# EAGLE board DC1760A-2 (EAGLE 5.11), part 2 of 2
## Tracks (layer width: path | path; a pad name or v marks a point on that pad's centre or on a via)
+3.3V  (via drill 0.61 pad 0.61)
  Top 0.254: 21.16,60.83 C39.2 | U2.8 12.67,61.33 12.78,61.21 12.78,60.96 12.72,60.9 | U2.5 12.29,59.83 12.75,60.29 C33.2 13.16,60.33 13.04,60.33 13.04,60.58 12.72,60.9 | U2.7 12.65,60.83 12.72,60.9 | U4.7 20.53,60.83 | U4.5 19.8,59.69 19.89,59.69
  Top 0.305: 13.16,60.33 13.54,60.33
  Top 0.381: U4.8 20.52,61.33 20.53,61.21 20.53,60.83 20.53,59.94 20.28,59.69 19.89,59.69
  Top 0.406: v22.56,60.83 21.16,60.83 20.53,60.83 | L1.1 27.51,66.02 27.51,71.12 TP2.1
  Top 0.61: 13.54,60.33 v14.05,60.33
  Bottom 0.305: 21.04,60.83 20.91,60.83
  Bottom 0.61: TP2.1 27.39,64.9 23.32,60.83 v22.56,60.83 21.04,60.83 20.66,60.83 19.13,62.36 16.08,62.36 v14.05,60.33
AIN+
  Top 0.203: U9.1 29.76,27.65 29.72,27.61 27.69,27.61 27.51,27.79 R40.2 27.53,27.74
AIN-
  Top 0.203: U9.2 29.83,27.15 29.75,27.23 27.69,27.23 27.49,27.03 27.51,27 R39.2
AMP_SHDN
  Top 0.203: 9.15,28.5 9.48,28.83 12.1,28.83 12.99,27.93 U10.P3
  Top 0.254: R17.2 9.11,28.31 9.1,28.32 9.15,28.12 9.15,28.5
AMP_VOCM  (via drill 0.25, 0.3)
  Top 0.203: v9.02,25.88 8.95,26.01 9.05,25.98 11.46,25.98 11.94,26.47 11.88,26.53 C57.1 12.27,26.9 12.91,26.9 12.91,26.89 U10.P5
  Top 0.406: 17.71,35.48 R11.1 | 17.91,35.28 R9.1 | 17.71,35.48 17.91,35.28 | R10.2 17.71,35.1 17.89,35.28 17.91,35.28 | 16.67,35.48 16.68,35.47 | 16.67,35.48 17.71,35.48 | v15.86,35.41 15.92,35.47 16.66,35.47 16.67,35.48
  Route4 0.254: 9.05,25.88 v9.02,25.88 9.15,26.01 10.8,26.01 13.87,29.08 13.9,29.08 | v15.86,35.41 15.83,35.41 13.89,33.47 13.89,29.08 13.9,29.08 | 13.9,29.08 13.93,29.08
CS  (via drill 0.25)
  Top 0.127: 32.77,19.63 v32.8,19.63 32.49,19.63 32.09,20.04 32.09,21.87 31.75,22.21 U9.13
  Route4 0.203: 40.62,23.57 40.62,28.45
  Route4 0.381: 45.55,58.5 45.55,58.42 | 45.62,58.5 45.55,58.5 | J4.4 45.55,58.57 45.55,58.5
  Route4 0.406: 45.51,58.58 45.52,58.6 45.62,58.5 46.59,57.53 46.59,53.67 | 46.59,53.67 46.59,53.6 | 46.59,53.67 46.59,53.59 43.92,50.93 43.92,37.36 43.44,36.88 41.36,36.88 41.1,36.63 40.8,36.63 40.34,36.17 40.34,34.54 40.62,34.27 40.62,28.45 | v39.86,16.49 39.81,16.49 39.81,16.56 40.62,17.37 40.62,23.57 40.62,23.55
  Bottom 0.254: R1.5 43.91,16.02 43.44,16.49 v39.86,16.49 39.86,16.46 35.97,16.46 v32.8,19.63
EXTREF  (via drill 0.25)
  Top 0.127: 28.05,31.39 29.55,31.39 30.84,30.1 30.84,29.06 31.25,28.65 U9.39
  Top 0.254: 25.79,34.77 25.79,34.75 | 25.79,34.77 25.79,39.5 v25.74,39.55 | 25.79,34.77 25.79,34.06 28.17,31.67 28.28,31.78 C17.1 28.28,31.73 28.05,31.5 28.05,31.39
  Bottom 0.254: R14.1 25.34,38.7 25.23,38.61 25.81,39.19 25.81,39.55 | v25.74,39.55 25.81,39.55 | TP1.1 24.09,42.14 24.11,42.16 24.09,42.16 24.03,42.11 24.03,41.35 25.81,39.55
GND  (via drill 0.25, 0.3, 0.41, 0.51, 0.61)  (6 unrouted)
  Top 0.127: 64.34,29.17 64.34,29.08 64.29,29.13 | 63.94,6.76 63.96,6.73 | v63.51,6.76 63.94,6.76 | 63.64,6.77 63.92,6.77 63.94,6.76 | 31.83,25.02 31.83,24.26 31.63,24.05
  Top 0.203: v63.73,45.95 63.71,45.97 J1.6 | 64.32,43.56 64.31,43.57 | 64.32,43.56 63.63,43.56 v63.61,43.59 | J1.12 64.32,43.56 | 65.64,38.74 65.74,38.74 | 65.64,38.74 J1.24 | v63.76,38.76 63.79,38.74 65.64,38.74 | J1.18 65.61,41.15 64.6,41.15 | 64.14,41.15 64.6,41.15 | v63.73,41.17 64.57,41.17 64.6,41.15 | 65.61,31.62 | 65.61,31.62 J1.42 | 64.42,31.55 65.54,31.55 65.61,31.62
  Top 0.254: 63.85,33.95 64.23,33.95 | 64.42,31.55 | v63.76,31.55 | v63.66,13.97 v63.65,13.97 | 63.74,29.17 63.79,29.21 v63.81,29.21 | 63.74,29.17 J1.48 | 63.74,29.17 63.73,29.16 | U9.3 28.61,26.65 v28.4,26.44 | v41.36,35.08 41.36,35.05 42.16,35.05 C35.2 | 8.03,58.62 7.7,58.62 7.7,57.91
  Top 0.305: 65.61,33.91 | 65.61,33.91 J1.36 63.89,33.97 63.84,33.91 v63.81,33.93 | 63.85,33.95 65.57,33.95 65.61,33.91 | 63.88,36.37 64.65,36.37 J1.30 | 63.68,26.7 63.68,26.72 65.57,26.72 J1.54 | C47.1 17.89,25.61 17.81,25.55 17.81,25.96 17.63,26.14 | 17.94,29.24 17.9,29.2 C45.1 17.79,28.88 17.61,28.7 v17.68,28.7 | 17.63,26.14 17.61,26.16 | 17.63,26.14 v17.66,26.14 | v18.32,26.44 18.35,26.44 18.74,26.05 C48.1 | v18.32,28.37 18.32,28.4 18.8,28.88 C46.1
  Top 0.356: 64.65,36.37 64.65,36.35 64.62,36.37 v63.94,36.37
  Top 0.406: 64.31,43.57 63.95,43.57 | 64.14,41.15 63.81,41.15 | 64.23,33.95 64.17,33.88 | v63.76,31.55 64.42,31.55 | 63.79,29.17 64.34,29.17 J1.48 | 64.98,11.56 v63.66,11.56 | 65.49,11.56 64.98,11.56 | 65.61,11.56 65.49,11.56 | 65.49,11.56 65.5,11.57 64.99,11.57 64.98,11.56 | J1.90 65.61,9.15 65.61,9.14 65.59,9.12 v63.66,9.12 | 65.61,11.56 J1.84 | 65.61,11.56 64.98,11.56 | v63.66,13.97 63.71,13.97 J1.78 | 65.61,6.73 | 65.61,6.73 J1.96 | 63.64,6.77 65.57,6.77 65.61,6.73 | R47.2 10.44,18.74 v10.78,19.08 | v7.65,58.09 7.96,58.04 7.96,58.62 8.03,58.62 8.08,58.67 8.03,58.73 R31.2
  Top 0.508: J1.60 65.53,21.17 65.49,21.21 65.46,21.18 v63.71,21.18 | 65.61,18.79 65.61,18.8 | J1.66 65.61,18.79 | v63.81,18.77 65.59,18.77 65.61,18.79 | J1.72 65.51,16.37 65.49,16.38 65.46,16.36 v63.71,16.36
  L2-GND 1.016: 23.32,-0.51 23.32,1.27
  Route3 1.016: 23.32,1.14 23.32,-0.51
  Route4 1.016: 23.32,1.02 23.32,-0.51
  L15-GND 1.016: 23.32,1.27 23.32,-0.51
  Bottom 0.127: 65.61,36.35 65.67,36.3 | 65.61,36.35 J1.30 | v63.94,36.37 65.59,36.37 65.61,36.35 | U1.3 59.9,13.85 59.57,14.17 v59.57,14.73 | C41.2 50.35,10.59
  Bottom 0.203: 63.35,28.98 v63.81,29.21 | 65.55,29.16 J1.48 | 65.64,29.97 J1.45 | 65.49,31.37 J1.42 | 65.49,31.37 63.46,31.37 | J1.37 65.49,32.97 63.79,32.97 | 63.35,33.78 v63.81,33.93 | 65.53,33.96 J1.36 | v63.76,31.55 arc90 63.58,31.37 v63.76,31.55 | J1.39 63.54,32.17 63.53,32.18 | 63.58,32.97 | 63.63,34.57 | 63.53,35.36 63.55,35.37 | 63.42,36.97 63.4,36.98 | 63.51,37.77 | 63.37,38.57 v63.76,38.76 | 63.38,39.37 | 63.43,40.18 63.44,40.17 | 63.46,40.97 v63.73,41.17 | 63.75,41.97 63.73,41.73 | 63.74,42.57 63.71,42.55 63.58,42.55 | 63.54,43.37 v63.61,43.59 | 63.51,44.35 63.51,44.17 | 63.49,44.97 63.48,44.96 63.46,44.98 | 65.49,31.37 63.58,31.37 v63.76,31.55 | 63.46,30.61 63.49,30.57 | v63.58,22.61 63.57,22.75 | 63.33,21.84 63.49,21.95 63.53,21.97 | 63.46,20.07 63.59,20.35 | 63.54,19.57 63.46,19.43 | 63.46,17.78 63.41,17.92 | 63.4,17.17 63.33,17.02 | 63.41,16.35 v63.71,16.36 | 63.46,15.37 63.46,15.57 | 63.59,14.77 63.58,14.61 | 63.4,14 v63.66,13.97 | 63.46,12.95 63.5,13.17 | 63.5,12.37 63.46,12.19 | v63.66,9.12 63.71,9.17 65.58,9.17 65.61,9.15 | v63.51,6.76 63.46,6.77 65.57,6.77 65.61,6.73 | 65.61,9.15 65.61,9.14 | 65.61,9.15 J1.90 | 65.61,6.73 | 65.61,6.73 J1.96 | 64.73,11.56 | 64.73,11.56 64.73,11.57 | 64.62,11.56 64.73,11.56 | 59.42,13.84 59.39,13.85 U1.2 59.31,13.85 U1.1 | 59.9,13.84 59.9,13.85 | 59.9,13.85 59.9,13.84 | U1.4 60.66,13.85 60.66,13.84 | 59.97,13.86 59.98,13.87 | U1.3 59.97,13.86 | 59.9,13.84 59.92,13.84 59.95,13.84 59.97,13.86
  Bottom 0.254: 63.83,47.57 63.58,47.32 63.58,46.61 | 63.58,46.61 63.58,46.08 63.71,45.95 | 63.58,46.61 63.61,46.61 63.76,46.77
  Bottom 0.305: 65.61,36.32 J1.30 | U1.7 59.32,8.96 59.14,9.14 57.61,9.14 57.49,9.02 57.36,9.02 57.4,8.98 C27.2 | 63.66,26.7 65.54,26.7 J1.54 | J1.54 65.61,26.75 | J1.54 J1.51 65.59,27.54 65.59,26.92 65.64,26.98 65.64,28.35 65.63,28.35 J1.49 | U7.7 48.62,9.53 | 47.99,8.26 U7.9 49.26,8.13 | U7.6 48.75,10.16 49.03,9.88 49.69,9.88 | U7.15 42.37,10.16 42.75,10.54 42.75,12.07 42.7,12.12 v42.68,12.09
  Bottom 0.406: 63.75,41.97 63.75,41.21 63.73,41.2 v63.73,41.17 | U1.2 59.42,13.84 59.92,13.84 59.9,13.85 | J1.85 62.27,10.77 60.48,12.55 60.48,13.79 60.54,13.85 U1.4 60.46,13.85 60.46,13.84 60.45,13.85 U1.3
  Bottom 0.508: 63.71,29.16 65.55,29.16 | 63.48,29.97 65.64,29.97 | 63.78,33.17 J1.37 | 63.79,33.96 65.53,33.96 | 63.68,34.77 J1.33 | 63.69,35.57 J1.31 | 63.56,37.17 J1.27 | 63.43,37.97 J1.25 | 63.66,38.77 J1.24 | 63.61,39.55 J1.21 | 63.61,40.37 J1.19 | 63.55,41.17 J1.18 | 63.75,41.97 65.47,41.97 | 63.81,42.77 J1.13 | 63.63,43.56 J1.12 | 63.51,44.35 J1.9 | 63.63,45.16 J1.7 | 63.68,31.57 J1.42 | 63.61,30.76 J1.43 | 63.57,22.75 J1.55 | 63.53,21.97 J1.57 | 63.57,21.17 J1.60 | 63.59,20.35 J1.61 | 63.54,19.57 J1.63 | J1.66 64.47,18.75 v63.81,18.77 | 63.41,17.92 J1.67 | 63.4,17.17 J1.69 | 63.41,16.35 J1.72 | 63.46,15.57 J1.73 | J1.75 63.59,14.77 | 63.4,14 J1.78 | 63.5,13.17 64.67,13.17 | 64.67,13.18 J1.79 | 64.63,11.57 64.73,11.57 J1.84 | v63.66,11.56 64.62,11.56 | 63.83,47.57 J1.1 | 63.76,46.77 J1.3 | J1.6 63.73,45.97 | 63.55,32.37 J1.39 | 63.5,12.37 63.58,12.37 63.59,12.37 J1.81 | R20.2 32.34,9.65 32.34,10.16 v32.57,10.39
  Bottom 0.61: v63.81,29.21 63.71,29.16 | 63.48,29.97 63.38,29.77 | 63.58,32.97 63.78,33.17 | v63.81,33.93 63.79,33.96 | 63.63,34.57 63.51,34.6 63.68,34.77 | 63.55,35.37 63.56,35.43 63.69,35.57 | 63.42,36.97 63.56,37.16 63.56,37.17 | 63.51,37.77 63.51,37.9 63.43,37.97 | 63.37,38.57 63.63,38.74 63.66,38.77 | 63.38,39.37 63.43,39.37 63.61,39.55 | 63.44,40.17 63.53,40.28 63.61,40.37 | 63.46,40.97 63.46,41.07 63.55,41.17 | 65.47,41.97 65.49,41.96 J1.15 | 63.74,42.57 63.74,42.7 63.81,42.77 | 63.54,43.37 63.54,43.47 63.63,43.56 | 63.49,44.97 63.49,45.02 63.63,45.16 | 63.58,31.37 63.58,31.47 63.68,31.57 | 63.49,30.57 63.49,30.64 63.61,30.76 | 63.57,21.17 v63.71,21.18 | 64.67,13.17 64.67,13.18 | 63.73,45.97 63.71,45.95 | 63.71,42.55 63.71,42.01 63.75,41.97 | 63.58,32.97 63.58,32.94 63.56,32.92 63.55,32.37 | 63.49,21.95 63.49,21.96 63.48,21.97 63.58,22.07 v63.58,22.61 | 63.46,15.37 63.46,15.29 63.43,15.27 63.59,15.1 63.59,14.77
  other vias: 28.23,34.72 29.17,37.59 28.71,38.74 34.93,37.82 29.24,44.3 32.42,36.86 46.69,34.95 42.91,42.24 43.01,41.4 42.55,37.87 50.35,11.43 49.05,19.13 15.17,17.12 14.13,51.82 9.23,11.79 15.5,7.26 28.23,8 15.5,9.3 15.5,10.19 15.63,11.07 13.98,16.41 3.05,28.73 48.47,17.17 48.7,14.88 54.64,10.08 54.97,7.52 59.29,12.22 35.59,35.2 32.57,41.02 32.21,35.2 20.99,38.35 20.22,69.06 17.76,39.14 17.91,54.28 22.23,50.44 17.86,45.97 19.01,39.17 36.25,40.06 38.08,38.2 37.78,39.67 37.8,40.64 40.42,43.26 37.04,39.17 41.51,39.09 26.75,36.25 24.95,35.15 21.85,34.9 24.57,35.66 20.43,43 21.8,47.35 19.16,69.93 19.16,71.32 19.16,72.72 19.16,73.99 8.52,74.07 7.22,73.99 11.41,73.99 9.76,73.99 8.11,72.72 2.5,9.04 1.99,8.1 3.38,8.51 1.1,7.37 4.96,8.59 0.97,8.76 8.21,5.94 7.07,1.02 8.59,4.06 9.61,4.45 10.88,3.81 12.15,1.91 13.42,1.91 14.69,1.91 15.96,1.91 19.97,15.88 17.51,38.07 30.36,69.32 29.04,73.86 27.72,73.89 32.65,50.14 31.38,53.42 27.64,50.57 28.33,52.86 27.26,62.71 31.07,42.44 35.29,69.67 36.05,70.18 36.81,70.94 37.57,71.7 38.46,72.59 46.41,38.38 42.27,42.49 45.83,35.69 46.62,35.66 41.28,35.81 41.99,35.81 44.91,42.24 44.91,43.66 59.8,67.61 48.24,73.1 46.97,73.1 45.7,73.1 44.43,73.1 43.16,73.1 41.89,73.1 40.62,73.1 39.48,73.1 40.72,42.19 42.83,39.98 44.91,41.43 37.55,35.18 41.61,38.18 41.64,1.02 43.26,0.97 50.65,6.58 42.5,2.67 50.65,2.08 45.02,8.41 50.76,0.89 52.03,0.89 53.3,0.89 54.69,0.89 55.84,0.89 57.23,0.89 58.5,0.89 59.65,1.65 60.28,2.41 58.48,2.62 53.4,2.59 54.95,3.81 52.15,7.52 49.13,8.1 50.3,7.7 46.92,8.71 53.8,17.25 59.65,11.68 46.39,39.34 41.87,40.59 41.94,41.3 60.31,10.16 59.11,17.91 54.44,16.84 54.9,16.18 48.42,44.27 39.15,36.63 40.57,38.56 39.73,37.47 55.84,3.02 46.49,14.76 42.7,12.88 43.01,14.73 30.08,46.38 25.79,47.75 29.45,47.85 28.23,45.34 27.77,48.54 27.26,46.33 30.31,43.31 30.87,36.86 26.9,38.81 34.75,35.76 0.84,67.01 30.36,72.36 33.74,43.64 32.72,40.13 35.21,45.09 35.64,37.87 35.85,41.78 36.4,43.28 31.55,50.06 26.32,40.82 30.38,38.74 19.72,45.95 30.44,37.52 32.87,38.96 33.76,42.6 32.39,44.04 33.28,45.31 30.38,70.97 16.36,16.74 14.94,15.34 0.87,31.14 16.31,12.12 24.52,36.4 24.49,37.19 21.72,37.67 23.88,45.47 20.28,39.24 25.81,50.47 18.78,37.97 15.27,51.79 15.02,45.67 27.87,37.31 18.4,43.31 12.78,53.19 11.46,54.38 24.82,44.4 24.49,48.08 21.88,35.74 13.09,16.28 9.25,44.65 9.73,45.49 42.55,19.56 33.79,44.65 32.59,46.08 32.59,47.45 32.62,48.9 32.65,51.36 32.65,52.68 32.65,54.03 32.65,55.17 32.65,56.34 32.14,57.3 31.35,58.06 30.46,58.93 30.41,60.02 30.49,61.19 28.28,63.63 30.44,62.23 30.49,63.27 30.46,64.39 30.36,67.34 28.89,64.41 26.27,58.67 24.64,58.7 25.36,60.78 24.77,60.05 26.8,54.28 26.35,61.8 22.87,59.23 20.68,62.87 25.13,64.57 25.84,65.28 25.08,67.44 25.94,67.44 24.95,73.89 26.35,73.91 22.31,67.54 20.96,67.54 18.19,63.75 21.95,62.15 19.49,67.56 22.74,62.2 23.45,57.53 23.5,56.31 17.3,58.95 22.54,45.95 23.63,54.74 23.6,53.64 23.63,48.84 35.36,40.92 35.21,46.43 35.24,47.5 35.21,48.67 35.26,49.94 35.29,51.23 35.34,52.68 35.29,54 35.26,55.45 35.26,56.79 35.26,58.17 35.21,59.39 35.21,62.33 35.26,63.3 35.24,64.24 35.24,65.23 35.19,66.27 35.26,68.78 58.32,66.73 56.57,66.55 55,67.01 53.7,67.92 52.97,69.09 14.46,14.76 59.8,65.46 59.8,64.14 59.8,62.46 59.8,60.96 59.75,59.64 59.8,58.32 59.92,56.67 59.92,54.99 59.95,53.67 59.9,52.32 60.08,50.93 59.95,49.48 59.98,47.88 59.98,46.61 59.32,46.13 17.79,73.99 16.21,74.04 14.64,74.09 13.14,74.04 18.24,67.49 18.22,66.22 18.24,64.87 21.22,58.93 18.12,58.12 23.48,58.72 21.65,55.91 21.88,54.48 17.86,55.58 22.79,53.54 11.77,8.79 16.59,48.62 21.77,48.31 1.07,46.99 1.12,48.31 1.15,51.05 1.12,53.82 1.12,55.17 1.17,56.79 1.12,58.37 1.17,59.97 2.09,59.97 0.92,66.04 0.9,68.05 5.77,66.88 8.01,69.01 39.05,41.5 38.31,41.48 39.6,49.12 50.45,49.3 38.74,61.98 39.22,67.08 42.7,43.74 41.36,45.14 42.83,49.23 44.91,47.55 50.5,46.63 50.48,47.55 52.05,46.99 55.78,48.49 55.71,46.89 57.54,46.91 42.68,51.92 49.59,61.54 42.73,64.49 42.65,70.05 46.31,67.21 55,62.18 48.6,56.82 44.81,49.89 54.84,62.97 41.74,62.18 49.77,64.14 49.31,70.21 52.23,67.18 46.62,62.46 52.99,62.74 51.52,54.05 57.33,58.29 48.55,58.39 56.88,63.78 42.98,43.13 42.68,44.58 58.12,46.02 58.12,46.99 56.57,55.55 56.57,53.98 57.61,55.63 55.94,47.78 52.81,16 15.78,57.79 14.15,54.28 15.27,53.24 14.08,53.21 16.06,39.45 12.17,43.15 9.86,47.73 12.81,54.31 12.86,55.42 12.58,62.51 9.38,49.1 10.12,50.47 7.98,48.29 7.32,54.86 6.08,53.44 3,57.58 4.17,54.81 8.08,46.33 5.72,46.18 11.46,55.52 43.69,7.59 42.78,6.17 41.61,3.23 21.8,36.78 19.64,36.68 19.87,38.07 19.16,41.94 37.8,36.63 40.65,37.59 35.62,35.94 35.26,36.63 44.89,43 29.8,36.09 11.28,49.28 20.91,44.93 29.78,39.62 26.65,37.54 31.6,46.46 31.38,55.09 29.67,51.64 26.65,49.63 30.31,50.62 11.74,36.88 10.29,55.47 9.07,51.54 11.28,37.67 15.07,38.18 15.09,36.75 17.74,32.54 2.88,45.85 7.3,53.87 16.26,38.46 16.62,50.19 1.07,15.16 6.38,12.47 2.5,10.85 1.12,10.74 7.37,7.19 6.33,8.1 8.01,9.7 4.32,10.64 6.18,10.9 6.33,13.79 4.27,15.16 1.91,19.3 9.58,16.1 62.9,6.96 61.37,15.29 62.92,11.99 62.9,14.33 63.05,16.03 62.8,17.07 63.05,20.09 62.87,20.9 61.07,6.3 62.87,4.95 61.47,10.06 62.19,12.65 62.16,14.94 62.21,17.65 44.91,46.79 63.23,33.68 44.91,45.16 45.6,45.09 46.11,46.18 62.87,41.17 46.01,46.86 62.59,47.27 61.86,46.56 63.33,47.65 61.93,47.68 61.17,47.68 45.17,46.05 60.53,21.77 62.41,20.35 62.49,16.46 9.63,10.74 24.44,1.02 12.45,40.21 19.56,51.26 11.44,56.62 8.06,52.5 12.78,56.64 15.22,50.22 24.54,51.77 20.61,37.24 41.64,19.53 63.53,17.2 50.7,17.6 47.58,17.09 28.96,34.72 31.78,41.76 27.21,41.53 28.35,40.26 26.96,40.01 50.6,40.39 50.58,42.21 50.48,45.09 50.55,43.71 51.11,44.32 51.24,41.12 50.6,39.22 42.5,45.36 46.49,45.19 48.42,46.38 51.75,45.36 51.64,42.7 55.68,45.21 56.8,45.36 44.86,48.64 42.68,46.38 46.36,44.02 37.88,47.47 41.56,48.18 39.45,46.15 38.69,51.49 41.1,50.72 37.9,53.04 11.59,62.46 10.67,62.43 11.59,63.3 10.65,63.32 11.11,58.7 10.19,57.71 10.19,58.72 11.33,57.71 10.19,56.57 4.68,55.52 5.57,55.52 6.46,55.52 21.95,66.07 21.95,65.05 21.95,64.16 21.95,63.27 3.79,55.52 18.9,58.93 18.14,58.93 18.88,58.12 12.5,63.37 7.09,67.77 11.16,46.13 5.11,54.81 5.98,54.79 6.28,56.39 3.05,56.41 12.66,48.01 1.07,49.71 15.02,42.57 8.97,8.56 10.5,7.04 9.23,6.65 8.69,16.1 52.89,12.85 55.71,12.95 52.79,10.54 54.95,14.22 45.7,41.99 46.39,42.77 61.02,46.13 58.25,24.13 28.86,67.36 25.15,66.27 29.65,67.31 25.89,66.27 21.09,62.23 24.01,59.44 13.11,58.72 12.35,58.72 13.87,58.72 21.88,58.93 20.61,58.95 13.49,61.82 18.62,44.5 37.42,24.94 31.4,31.19 28.51,29.77 25.53,24.13 25.53,23.29 48.01,27.08 29.09,28.35 28.4,28.35 26.37,28.78 25.53,24.87 22.31,24.66 22.46,30.07 36.07,22.15 38.11,30.12 30.03,21.67 26.63,24.16 28.89,19.84 28.2,19.84 27.69,20.19 38.18,24.92 38.89,24.92 39,25.78 39.2,30.4 41.74,27.38 36.68,25.12 32.59,31.24 33.15,30.48 30.71,31.09 28.38,29.13 27.57,34.72 42.55,28.93 41.79,28.93 43.26,32.31 44.48,32.28 43.82,31.62 43.21,30.91 44.46,30.86 43.87,30.25 43.26,24.18 44.46,24.16 43.85,23.44 43.24,22.81 44.46,22.83 43.87,22.15 42.5,27.38 41.71,26.7 45.65,27.33 46.39,26.54 46.39,27.28 52.71,1.78 53.37,1.93 31.78,19.56 29.67,21.18 26.12,26.01 25.53,26.04 24.85,26.01 29.09,26.44 25.69,28.78 25,28.78 24.34,29.08 23.78,29.64 23.15,30 24.21,25.6 23.7,25.04 23.04,24.69 21.11,24.71 20.94,23.95 20.3,23.44 20.28,20.5 18.5,17.88 16.11,18.06 15.22,18.67 14.41,20.24 11.21,17.55 11.84,18.24 13.8,20.47 11.79,20.37 11.74,21.18 11.82,19.69 11.79,19 10.39,16.46 7.98,16.08 6.13,15.19 5.32,15.19 2.98,15.16 0.97,19.33 3.03,19.3 4.3,19.3 5.49,19.3 6.33,19.89 6.31,20.88 6.33,22.07 6.33,23.34 6.33,24.87 6.33,26.42 6.71,28.17 6.71,29.85 6.71,31.32 6.71,32.89 6.71,34.29 5.75,35.59 4.5,35.61 3.18,35.59 1.4,35.61 1.15,39.55 3.08,39.55 4.5,39.52 5.9,39.52 9.81,41.96 9.84,39.65 11.54,39.5 11.97,37.57 15.07,39.27 11.77,36.07 11.77,35.41 9.33,40.84 11.79,34.75 15.98,36.68 15.78,32.46 18.22,33.1 18.95,32.89 18.62,33.73 19.95,32.84 20.53,33.48 21.19,33.05 19.56,49.3 25.08,30.56 24.44,2.29 24.44,3.56 24.44,4.83 24.44,6.1 28.51,6.15 28.51,4.88 28.51,3.61 28.51,2.34 28.51,1.07 25.33,6.55 26.6,6.55 27.87,6.55 33.03,2.51 33.03,3.78 33.03,5.05 33.03,6.32 34.3,6.45 35.59,6.43 36.84,6.32 36.96,5.05 36.96,3.78 36.96,2.51 36.96,1.24 33.03,1.24 28.73,8.51 28.99,10.29 28.96,11.33 28.96,12.34 28.96,13.61 28.96,14.88 28.96,16.15 28.96,17.42 28.96,18.44 29.55,19.23 32.82,8.03 32.95,9.42 32.54,11.33 35.06,11.35 32.54,12.34 32.54,13.61 32.54,14.88 32.54,16.15 32.54,17.17 32.42,18.57 31.93,18.97 50.65,37.82 52.05,39.24 53.83,41.05 56.09,43.31 57.72,44.93 50.88,21.89 52.79,23.83 53.7,24.74 55.68,26.75 56.88,27.69 58.93,27.71 59.87,27.58 51.37,30.84 55.84,19.84 54.36,21.54 57.54,21.13 56.95,16.61 40.16,1.65 40.16,3.48 40.24,5.99 40.21,8.18 40.27,10.08 40.16,12.07 38.69,13.61 37.55,14.91 40.6,14.73 39.99,13.69 25.03,15.24 22.21,11.3 20.96,11.73 18.62,10.19 19.72,14.25 22.03,19.28 22.84,15.52 19.46,18.9 24.09,19.94 25.41,19.05 24.11,17.5 24.95,20.96 22.89,20.47 20.28,18.01 17.25,18.08 14.59,18.75 10.73,17.09 17.81,12.12 24.8,9.65 24.26,13.18 27.67,12.4 21.6,8.71 21.16,6.02 17.23,1.91 18.5,1.91 19.77,1.91 21.04,1.91 22.31,1.91 22.82,2.51 22.84,5.03 22.84,6.3 22.84,7.57 24.06,7.98 25.2,7.98 26.35,7.98 27.36,7.98 17.74,14.48 2.5,26.49 4.07,24.89 4.96,28.47 1.66,28.24 1.68,24.82 4.2,26.67 1.17,43.94 1.07,45.62 2.44,43.94 3.71,43.94 4.98,43.94 6.25,43.94 6.25,40.13 6.51,41.4 8.26,44.91 8.26,43.64 8.24,41.83 8.44,39.95 10.9,40.84 20.76,50.8 27.74,55.17 33.84,8.03 35.11,8.03 36.38,8.03 33.53,13.87 34.73,12.67 35.95,11.46 36.58,10.06 52.71,31.62 53.83,32.66 55.78,34.37 56.95,35.84 58.3,37.24 59.42,38.51 58.1,38.58 61.91,38.76 60.97,38.76 56.67,38.61 55.71,37.47 53.63,35.64 53.17,34.98 52.33,34.26 51.57,33.45 50.73,32.64 50.65,31.67 59.19,31.6 61.42,31.55 59.57,34.01 61.88,33.93 60.59,36.5 62.54,36.47 59.67,43.64 61.93,43.61 58.66,41.15 61.3,41.17 6.51,42.67 31.35,27.03 32.37,27.03 33.38,27.03 34.4,27.03 34.4,26.01 34.4,24.99 34.4,23.98 31.35,26.01 31.35,24.99 31.35,23.98 32.37,23.98 32.37,24.99 32.37,26.01 33.38,26.01 33.38,24.99 33.38,23.98 39.91,24.92 39.91,25.76 39.91,27.13 42.04,25.68 41.36,25.68 10.24,26.59 17.41,27.48 37.19,30.73 36.89,29.21 36.4,28.7 39.78,30.86 38.49,30.81 37.47,29.72 37.09,21.44 36.63,20.96 37.88,21.54 37.45,20.9 36.58,20.17 27.03,28.78 27.72,28.78 27.49,26.01 26.83,26.04 10.8,35.74 10.73,34.32 10.75,19.89 12.81,26.29 12.76,29.24 18.19,27.41 18.88,27.41 19.59,27.43 20.25,27.46 20.96,27.28 17.02,28.22 16.67,25.96 16.97,26.7 16.62,28.91 12.15,25.73 15.3,26.16 15.12,28.55 19.62,23.44 18.9,23.44 18.19,23.44 17.51,23.47 16.82,23.47 16.14,23.47 15.45,23.44 14.61,22.45 15.45,22.63 13.8,22.2 12.81,22.17 12.07,22.2 10.39,22.81 12.71,21.46 10.8,22.38 11.44,22.25 20.81,31.32 23.07,30.96 20.07,31.37 19.36,31.34 18.62,31.34 17.94,31.34 17.2,31.34 16.49,31.37 15.81,31.34 15.2,31.57 15.12,32.26 10.78,39.01 12.76,32.99 11.79,41.73 11.82,33.93 11.54,32.28 10.55,31.95 11.03,32.82 11.82,33.2 10.62,37.74 10.01,38.02 9.53,38.56 8.85,38.66 8.19,38.66 6.74,38.71 7.88,36.45 8.36,35.89 8.36,35.13 8.36,34.29 8.36,33.43 8.36,32.72 8.36,31.93 8.36,31.24 8.39,30.53 8.72,29.79 7.98,18.44 8.36,18.95 8.34,19.66 8.34,20.37 8.36,21.13 8.36,21.87 8.36,22.61 8.34,23.39 8.31,24.08 8.31,24.77 8.24,25.35 17.05,21.26 21.44,21.97 23.32,22.58 17.1,20.22 18.35,16.31 9.89,13.77 22.41,13.54 27.79,16.03 12.71,35.28 12.71,37.47 12.73,38.25 16.77,32.39 21.22,31.83 21.62,32.41 24.26,31.04 24.87,29.67 26.02,29.57 12.71,44.32 48.37,52.22 51.87,51.38 53.75,51.41 44.38,53.47 39.2,54.71 39.22,64.85 46.92,65.51 53.37,66.04 45.42,71.25 10.75,28.27 10.04,28.27 9.96,27.53 9.53,26.62 10.85,35 10.73,20.6 13.93,27.76 13.93,27.03 12.71,32.26 9.81,25.3 11.36,25.43 10.62,25.3 9.86,29.39 10.75,29.39 11.69,29.39 60.03,24.89 60.03,23.88 60.53,22.86 61.55,22.61 62.57,22.61 60.03,25.91 60.53,26.67 61.55,26.67 62.57,26.67 63.58,26.67 15.07,57.79 6.51,58.85
  pour Bottom (isolate 0.254, no thermals): 0.59,74.42 0.59,0.51 37.29,0.51 37.29,11.05 33.36,14.99 33.36,38.1 34.12,38.86 34.12,45.72 33.1,46.74 33.1,57.15 30.82,59.44 30.82,72.9 29.29,74.42
  pour Bottom (isolate 0.254, no thermals): 34.88,38.35 34.37,37.85 34.37,29.46 33.36,28.45 33.36,21.84 34.37,20.83 34.37,16.76 39.71,11.43 39.71,0.51 60.53,0.51 60.53,4.57 64.09,4.57 64.09,23.11 61.3,23.11 arc-90 60.53,23.88 60.53,25.65 arc-90 61.3,26.42 64.09,26.42 64.09,48.01 60.53,48.01 60.53,74.42 39.2,74.42 34.88,70.1
  pour Top (rank 2, no thermals): 33.38,14.81 33.36,20.78 33.41,21.54 33.48,28.63 33.46,32.05 33.46,38.2 34.14,38.89 34.14,45.11 33.15,46.08
  pour L2-GND (isolate 0.381, rank 2): 0.59,74.42 60.53,74.42 60.53,48.26 67.14,48.26 67.14,26.42 61.3,26.42 arc90 60.53,25.65 60.53,23.88 arc90 61.3,23.11 67.14,23.11 67.14,4.57 60.53,4.57 60.53,0.51 0.59,0.51 0.59,15.75 6.18,15.75 6.94,16.51 9.48,16.51 9.99,17.02 9.99,23.11 10.24,23.37 13.54,23.37 13.8,23.62 13.8,24.89 13.54,25.15 9.23,25.15 8.72,24.64 8.72,18.54 8.21,18.03 6.94,18.03 6.18,18.8 0.59,18.8 0.59,36.07 5.92,36.07 6.69,36.83 8.21,36.83 8.72,36.32 8.72,30.23 9.23,29.72 13.8,29.72 13.8,31.5 10.24,31.5 9.99,31.75 9.99,37.34 8.97,38.35 6.69,38.35 5.92,39.12 0.59,39.12
  pour Route3 (isolate 0.381, rank 2): 0.59,59.06 23.2,59.06 23.2,74.42 60.53,74.42 60.53,48.26 67.14,48.26 67.14,26.42 61.3,26.42 arc90 60.53,25.65 60.53,23.88 arc90 61.3,23.11 67.14,23.11 67.14,4.57 60.53,4.57 60.53,0.51 0.59,0.51
  pour Route4 (isolate 0.381): 0.59,74.42 60.53,74.42 60.53,48.26 67.14,48.26 67.14,26.42 61.3,26.42 arc90 60.53,25.65 60.53,23.88 arc90 61.3,23.11 67.14,23.11 67.14,4.57 60.53,4.57 60.53,0.51 0.59,0.51
  pour L15-GND (isolate 0.381): 0.59,74.42 60.53,74.42 60.53,48.26 67.14,48.26 67.14,26.42 61.3,26.42 arc90 60.53,25.65 60.53,23.88 arc90 61.3,23.11 67.14,23.11 67.14,4.57 60.53,4.57 60.53,0.51 31.83,0.51 31.83,18.54 29.8,18.54 29.8,0.51 0.59,0.51
  pour Top (rank 2, no thermals): 0.59,74.42 0.59,0.51 37.29,0.51 37.29,11.05 33.36,14.99 33.36,38.1 34.12,38.86 34.12,45.72 33.1,46.74 33.1,57.15 30.82,59.44 30.82,72.9 29.29,74.42
  pour Top (no thermals): 34.88,38.35 34.37,37.85 34.37,29.46 33.36,28.45 33.36,21.84 34.37,20.83 34.37,16.76 39.71,11.43 39.71,0.51 60.53,0.51 60.53,4.57 64.09,4.57 64.09,23.11 61.3,23.11 arc-90 60.53,23.88 60.53,25.65 arc-90 61.3,26.42 64.09,26.42 64.09,48.01 60.53,48.01 60.53,74.42 39.2,74.42 34.88,70.1
N$1
  Bottom 0.254: R1.1 45.5,14.96 45.75,14.71 45.75,8.38 46.51,7.62 U7.10
N$2  (via drill 0.3 pad 0.61)
  Top 0.254: U9.11 30.75,20.57 v30.69,20.57
  Bottom 0.508: 30.69,9.4 v30.69,20.57 | 30.69,9.4 R20.1 | 30.69,9.4 R13.1 | R19.2 30.69,9.4
N$3  (via drill 0.25)
  Top 0.127: 55.96,4.83 R24.2 55.9,4.77 | 55.96,4.83 56.02,4.77 56.66,4.77 56.98,4.45 v56.98,3.81 | 55.9,4.77 55.96,4.83 | 55.9,4.77 55.84,4.7 U6.2 53.22,4.7
  Bottom 0.127: 65.36,5.08 65.49,4.95 J1.99 65.61,5.21 | 65.61,5.21 | 65.61,5.21 65.51,5.11 63.71,5.11 63.28,5.54 62.01,5.54 60.03,3.56 57.23,3.56 v56.98,3.81
N$4
  Bottom 0.508: R13.2 30.82,7.62 30.77,7.57 J7.1
N$5
  Bottom 0.254: U7.11 42.55,7.62 44.96,10.03 R1.2 | R1.2 44.96,14.99 | R1.2
N$6
  Bottom 0.203: R4.1 55.31,60.47
  Bottom 0.381: R4.1 53.73,60.4 J2.2
N$7
  Top 0.254: 7.96,59.56 7.99,59.65 R31.1 7.96,59.53 7.96,59.55 | U2.4 8.22,59.83 7.96,59.56 | C19.1 7.96,59.68 | 7.96,59.68 7.96,59.69 | 7.96,59.68 7.96,59.55 | 7.96,59.55 7.96,59.56
N$8
  Bottom 0.254: U7.12 42.42,8.26 44.46,10.29 44.46,14 44.46,14.94 44.48,14.96 R1.3
N$9
  Top 0.305: J8.1 3.16,37.54 | J8.1 | C21.1 J8.1
N$10
  Top 0.254: 15.9,59.5 16.08,59.44 15.32,59.44 C22.1 | 15.9,59.5 R3.1 | U4.4 16.22,59.83 15.9,59.5
N$11
  Bottom 0.381: 51.54,60.6 51.64,60.71 | 51.54,60.6 J2.1 | R33.1 51.34,60.4 51.54,60.6
N$12  (via drill 0.3)
  Top 0.406: R17.1 8.13,28.27 8.13,27.69 v8.36,27.41
  Route4 0.406: J10.1 11.46,15.11 7.55,15.11 6.99,15.67 6.99,18.85 7.32,19.18 7.32,26.39 8.36,27.43 | 8.36,27.43 v8.36,27.41 | 8.36,27.43 8.36,27.38
N$13
  Top 0.254: R12.1 31.46,21.45 31.25,21.66 U9.12
N$15
  Top 0.254: 14.32,26.05 U10.P7 14.36,26.03 14.36,25.71 14.66,25.71 15.4,24.96 R54.2
  Top 0.305: 14.33,26.06 U10.P7 14.31,26.06 14.31,24.89 | 14.31,23.88 14.36,23.93 arc45 14.43,23.75 14.46,23.73 | C2.2 14.31,24.89 | 14.46,23.73 arc45 R57.1 arc-45 14.46,23.73 | 14.31,24.89 14.31,23.98 arc45 14.38,23.8 14.46,23.73 | 14.46,23.73 14.56,23.62
N$16
  Bottom 0.254: R1.4 43.91,10.55 42.88,9.53 U7.14
  Bottom 0.305: R1.4 43.95,15.01 43.96,15
N$18
  Top 0.254: R49.2 15.38,29.83 14.89,29.34 14.36,29.34 14.32,29.55 U10.P1
  Top 0.305: 14.26,29.85 14.28,29.85 arc-45 14.32,29.75 14.32,29.55 | C5.2 14.26,29.85 | R58.2 14.42,30.11 arc-45 14.34,29.93 14.26,29.85
N$25
  Bottom 0.381: 43.24,60.68 43.26,60.71 | J4.1 43.24,60.68 | R32.1 42.96,60.4 43.24,60.68
N$26
  Top 0.305: R56.1 21.78,25.98 21.77,25.98 21.78,26 22.94,26 22.94,25.94 | 22.79,25.96 22.88,25.96 R53.2 | R53.2 23.14,26 23.15,25.98 24.06,26.9 26.22,26.9 | 22.94,25.94 22.94,25.91 | R53.2 22.94,25.94 | 26.22,26.9 26.2,26.88 C18.1 26.12,26.92 26.16,26.96 R39.1 | 26.22,26.9 26.24,26.92
N$27
  Bottom 0.254: R35.1 47.05,60.43 46.82,60.45
  Bottom 0.381: J4.2 45.24,60.66 45.29,60.45 45.57,60.43 47.05,60.43
N$28
  Top 0.127: U9.5 | U9.5 U9.4 | U9.5 30.05,25.66 29.95,25.76
  Top 0.203: 28.51,25.32 28.45,25.32 28.45,24.92 C3.2
  Top 0.406: 30,26.01 30,25.76 29.95,25.76 29.47,25.76 28.86,25.15 29.11,25.38 | 29.11,25.38 28.86,25.04 | 28.51,25.32 28.53,25.3 C1.1 28.96,25.3 29.04,25.38 29.11,25.38
  pour Top (no thermals): 29.29,25.5 30.31,25.5 30.31,26.39 29.62,26.39 29.62,25.76 28.12,25.76 28.12,25.32 26.85,25.32 26.85,24.82 29.29,24.82
N$29
  Top 0.254: C1.2 28.61,23.83 29.43,24.65 U9.7
  pour Top (no thermals): 27.01,23.09 29.01,23.09 29.01,24.46 30.33,24.46 30.33,25.22 29.57,25.22 29.57,24.51 28.12,24.51 28.12,23.55 27.01,23.55
N$30
  Top 0.127: R5.1 34.72,29.76 33.75,28.79 U9.34
  Top 0.203: R5.1 34.72,29.83
N$31
  Top 0.127: R5.2 35.27,29.72 34.25,28.71 U9.33
  Top 0.203: R5.2 35.27,29.9
N$32
  Top 0.127: R5.3 35.77,29.7 35.77,29.69 34.75,28.67 U9.32
N$33
  Top 0.127: 31.71,28.35 U9.38
  Top 0.203: C14.2 31.44,29.53 31.71,29.26 31.71,28.35
N$34
  Top 0.127: R5.4 36.32,29.65 35.25,28.59 U9.31
N$35
  Top 0.127: R5.8 34.72,31.79 36,33.07 42.12,33.07 U3.3
N$36
  Top 0.127: R5.7 35.27,31.75 36.07,32.56 U3.4 42.1,32.56 | 42.1,32.56 42.12,32.54 | 42.1,32.56 U3.4
N$37
  Top 0.127: R5.6 35.77,31.49 36.33,32.06 42.04,32.06 42.06,32.07 U3.5
N$38
  Top 0.127: R5.5 36.32,31.38 36.51,31.57 42.04,31.57 42.05,31.57 U3.6
N$39
  Top 0.127: R6.1 37.69,28.97 36.37,27.65 U9.30
N$40
  Top 0.127: R6.8 39.21,28.97 41.31,31.06 42.07,31.06 42.07,31.07 U3.7
N$41
  Top 0.127: R6.2 37.6,28.42 36.33,27.15 U9.29
N$42
  Top 0.127: R6.7 39.17,28.42 41.31,30.56 42.02,30.56 42.03,30.57 U3.8
N$43
  Top 0.127: R6.3 37.58,27.92 36.31,26.65 U9.28
N$44
  Top 0.127: R6.4 37.64,27.37 36.42,26.15 U9.27
N$45
  Top 0.127: R6.6 39.35,27.92 41.51,30.07 42.12,30.07 42.11,30.07 U3.9
N$46
  Top 0.127: R6.5 39.19,27.37 41.38,29.57 42.2,29.57 42.19,29.57 U3.10
N$47
  Top 0.127: U9.24 35.96,24.59 36.48,24.59 37.01,24.05 37.8,24.05 R7.1
N$48
  Top 0.127: U9.23 36.51,24.15 37.14,23.52 R7.2
N$49
  Top 0.127: U9.22 36.48,23.65 37.09,23.04 37.75,23.04 37.78,23.01 37.78,23.02 R7.3
N$50
  Top 0.127: U9.21 36.47,23.15 37.17,22.45 37.8,22.45 R7.4
N$51
  Top 0.127: R7.8 40.1,24.07 40.9,24.87 42.07,24.87 42.07,24.86 U5.3
N$52
  Top 0.127: R7.7 40.19,23.52 41.05,24.38 42.07,24.38 U5.4
N$53
  Top 0.127: R7.6 40.27,23.02 41.1,23.85 41.94,23.85 41.96,23.86 U5.5
N$54
  Top 0.127: R7.5 40.15,22.47 41.05,23.37 42.14,23.37 42.14,23.36 U5.6
N$55
  Top 0.127: U9.20 35.25,21.83 35.77,21.31 35.77,20.8 35.79,20.78 R8.1
N$56
  Top 0.127: R8.8 35.81,19.39 36.07,19.13 36.63,19.13 38.92,21.41 39.88,21.41 41.31,22.84 42.12,22.84 U5.7
N$57
  Top 0.127: R8.2 35.26,21.24 34.75,21.75 U9.19
N$58
  Top 0.127: R8.7 35.26,18.98 35.41,18.82 36.79,18.82 38.97,21.01 40.01,21.01 41.36,22.35 U5.8
N$59
  Top 0.127: R8.3 34.76,21.23 34.25,21.74 U9.18
N$60
  Top 0.127: R8.6 34.76,18.92 35.16,18.52 36.94,18.52 39.02,20.6 40.06,20.6 41.33,21.87 42.17,21.87 42.16,21.86 U5.9
N$63
  Top 0.127: R8.4 33.75,21.25 U9.17
N$64
  Top 0.127: R8.5 34.21,19.01 35.08,18.14 37.04,18.14 39.12,20.22 40.16,20.22 41.31,21.36 42.14,21.36 U5.10
N$65
  Top 0.127: U3.21 46.75,32.57 59.34,45.16 65.67,45.16 65.66,45.17 J1.8
N$66
  Top 0.127: U3.20 46.73,32.07 59.04,44.37 65.72,44.37 65.71,44.37 J1.10
N$67
  Top 0.127: U3.19 46.92,31.57 58.12,42.77 65.56,42.77 65.59,42.75 J1.14
N$68
  Top 0.127: U3.18 46.92,31.07 57.84,41.99 65.56,41.99 65.59,42.01 65.61,41.99 J1.16
N$69
  Top 0.127: U3.17 46.91,30.57 56.75,40.41 65.74,40.41 65.7,40.37 J1.20
N$70
  Top 0.127: U3.16 46.97,30.07 56.47,39.57 65.49,39.57 65.5,39.57 J1.22
N$71  (via drill 0.25)
  Top 0.127: U3.15 47.53,29.57 47.53,29.59 47.56,29.59 v47.73,29.77 | J1.50 65.68,28.37 65.69,28.37 v62.31,28.37
  Top 0.254: J1.50 65.69,28.3 65.67,28.27
  Bottom 0.127: v47.73,29.77 48.09,29.41 60.69,29.41 61.73,28.37 v62.31,28.37
N$72  (via drill 0.25)
  Top 0.127: U3.14 47.49,29.02 v47.73,28.78 | 65.86,27.57 65.87,27.56 | 65.86,27.57 J1.52 | v62.31,27.58 65.84,27.58 65.86,27.57
  Top 0.254: J1.52 65.42,27.57 65.31,27.46 65.06,27.71
  Bottom 0.127: v47.73,28.78 48.06,29.11 60.46,29.11 61.98,27.58 v62.31,27.58
N$73
  Top 0.127: U5.21 46.87,24.36 60.48,37.97 65.56,37.97 65.61,37.92 | 65.61,37.92 65.64,37.9 | 65.61,37.92 J1.26
N$74
  Top 0.127: U5.20 46.93,23.86 60.23,37.16 65.49,37.16 65.51,37.19 65.53,37.17 J1.28
N$75
  Top 0.127: U5.19 47.17,23.36 59.37,35.56 65.87,35.56 | 65.87,35.56 65.86,35.57 J1.32 | 65.87,35.56 65.92,35.51
N$76
  Top 0.127: U5.18 47.46,22.86 59.37,34.77 65.51,34.77 65.59,34.7 65.61,34.72 J1.34
N$77
  Top 0.127: U5.17 47.67,22.36 58.45,33.15 65.64,33.15 J1.38
  Top 0.203: J1.38 65.51,33.17 65.44,33.1 65.39,33.15 63.51,33.15
N$78
  Top 0.127: U5.16 47.88,21.86 58.38,32.36 65.69,32.36 65.69,32.37 J1.40
N$79
  Top 0.127: U5.15 48.07,21.36 57.46,30.76 J1.44 | J1.44 | J1.44 65.67,30.71
N$80
  Top 0.127: U5.14 48.25,20.81 57.41,29.97 65.79,29.97 | 65.79,29.97 J1.46 | 65.79,29.97 65.82,30
N$82
  Top 0.127: C13.1 32.43,29.53 31.93,30.02 31.93,32 31.96,32 32.03,32.07 31.97,32.07 | C13.1 32.47,29.54 32.44,29.52 | 32.25,29.5 32.43,29.5 32.44,29.52 | 32.44,29.52 32.45,29.53 C13.1 | 32.44,29.52 32.44,29.64
  Top 0.203: 32.44,29.64 32.42,29.67 | U9.37 32.25,29.5 | 31.97,32.07 R15.1
N$92
  Top 0.203: C21.2 9.25,37.57 9.38,37.44 9.38,36.55 9.4,36.53 R42.1
  Top 0.305: R42.1 9.49,36.55 9.48,36.55 R41.1
N$94  (via drill 0.25)
  Top 0.254: v45.02,36.04 45.04,36.04 44.99,35.99 | v44.72,27.7 v44.71,27.71 44.71,27.69 | 44.71,27.69 44.74,27.66 44.72,27.65 | U3.24 44.15,34.67 44.28,34.8 45.04,34.8 | 45.04,34.8 45,34.84 C34.1 45,34.8 45.04,34.8 | U3.23 44.65,34.8 45.04,34.8 | U5.24 44.16,25.4 U5.23 44.65,26.73 44.71,26.8 44.72,26.79 C36.1 44.7,27.69 44.71,27.69 | 44.71,27.69 44.79,27.69
  Top 0.305: 45.02,34.95 C34.1 44.94,34.95 | 44.94,34.95 44.89,34.9 | 44.99,35 44.94,34.95 | L1.2 29.28,65.88 29.29,66.04 29.39,65.94 v30.23,65.94 | 44.99,35.99 44.99,35 | 44.99,35 44.99,36.02 45.07,36.09
  Route3 0.203: 44.99,36.04 v45.02,36.04 | v44.71,27.71 44.68,27.71
  Route3 0.406: 44.99,36.04 45.35,36.4 47.45,36.4 | 47.48,36.4 47.5,36.4 | 44.68,27.71 45.27,28.3 46.64,28.3 46.87,28.07 48.39,28.07 49.69,29.36 49.69,32.49 47.45,34.72 47.45,36.4 | 47.45,36.4 47.45,36.42 | 47.45,36.4 47.48,36.4 | v30.23,65.94 30.23,65.86 47.48,48.62 47.48,36.4
N$96
  Top 0.127: U9.35 33.25,28.88 34.04,29.67 34.04,32.18 34.11,32.25 | 34.11,32.25 34.12,32.26 | 34.11,32.25 R16.2
N$97
  Top 0.305: J9.1 3.3,17.23 3.31,17.25 3.33,17.23 C42.1
N$98
  Top 0.203: C42.2 9.28,17.23 9.43,17.37 9.43,18.16 R47.1
  Top 0.305: R47.1 9.49,18.2 9.48,18.19 R46.1
N$99
  Top 0.305: C43.1 9.48,33.5 9.49,33.5 R43.1 9.48,33.53 9.48,34.54 9.49,34.57 9.48,34.57 R41.2
N$101
  Top 0.305: C44.1 9.48,21.23 9.49,21.25 R48.1 9.48,21.27 9.48,20.32 9.49,20.18 9.48,20.17 R46.2
N$102
  Top 0.305: U10.P6 13.52,25.21 arc45 13.54,25.15 arc-45 13.61,25 C2.1 13.61,24.79 | 13.54,24.64 arc45 13.61,24.79 | R59.2 13.26,24.45 arc45 13.43,24.53 13.54,24.64 | 13.54,24.64 arc45 13.61,24.79 | R57.2 13.42,24.41 arc-45 13.5,24.59 13.54,24.64
N$103
  Top 0.127: U9.36 32.75,28.83 33.69,29.77 33.69,31.98 33.53,32.13 R16.1
N$104
  Top 0.305: R60.2 12.5,30.3 arc45 12.68,30.38 13.28,30.98 arc-45 R58.1 13.42,29.95 arc45 13.5,29.77 13.54,29.72 | 13.56,29.73 arc45 C5.1 arc-45 13.56,29.73 | 13.54,29.72 13.56,29.73 | U10.P2 13.52,29.66 arc-45 13.54,29.72
N$106
  Top 0.254: R50.2 18.91,30.01 arc-90 18.88,29.97 arc90 18.8,30.05 17.81,30.05
  Top 0.305: C45.2 17.79,30.07 17.81,30.05 17.8,30.04 R49.1
N$107
  Top 0.305: 20.9,28.76 R51.2 20.84,28.89 | R50.1 19.91,28.97 19.86,28.92 C46.2 20.83,28.88 20.84,28.89 | 20.84,28.89 20.91,28.96
N$108
  Top 0.305: R51.1 21.79,28.82 21.78,28.81 | 21.78,28.81 21.77,28.8 | 26.93,27.71 26.96,27.74 R40.1 26.94,27.75 26.18,27.75 26.12,27.81 26.12,27.82 C18.2 25.99,27.87 | 22.94,28.86 22.94,28.96 | 22.94,28.86 R52.1 23.15,28.81 23.17,28.83 24.15,27.85 25.99,27.85 25.99,27.87 | 21.78,28.81 22.94,28.81 22.94,28.86 | 25.99,27.87 25.99,27.94
N$110
  Top 0.305: R54.1 17.8,24.75 17.81,24.74 17.79,24.71 C47.2 17.86,24.64 17.86,24.73 18.88,24.73 18.88,24.86 | 18.88,24.86 18.88,24.89 | 18.88,24.86 R55.2
N$111
  Top 0.305: 20.85,25.92 20.9,26 R56.2 20.9,26.15 arc-90 20.91,26.16 arc-90 20.8,26.05 C48.2 19.86,25.91 19.91,25.91 R55.1 19.86,24.78 19.84,24.77 19.83,24.78
N$114
  Top 0.305: C44.2 9.48,24.28 9.66,24.46 11,24.46 11,24.45 R59.1
N$115
  Top 0.305: C43.2 9.48,30.84 arc45 9.55,30.66 9.99,30.23 11.51,30.23 11.48,30.26 arc45 R60.1
OUT-ENABLE  (via drill 0.25)
  Top 0.127: U6.4 51.48,5.35
  Top 0.254: U6.4 51.53,5.35 51.48,5.4 R18.2 | v46.39,33.55 46.34,33.55 45.85,33.07 U3.22 | v46.92,25.53 46.92,25.5 46.28,24.86 U5.22
  Top 0.305: v51.64,13.54 51.64,13.56 51.47,13.39 51.47,13.34
  Top 0.406: 51.48,5.35 51.47,5.36 51.47,13.34
  Route3 0.305: 47.48,25.65 47.45,25.65
  Route3 0.406: v51.64,13.54 51.64,22.81 48.8,25.65 47.48,25.65 47.07,25.65 46.95,25.53 v46.92,25.53
  Route4 0.406: v46.92,25.53 46.92,25.68 47.22,25.98 47.22,26.11 | 47.22,26.11 47.22,26.06 | 47.22,26.11 47.22,27.76 46.16,28.83 46.16,33.33 v46.39,33.55
OVDD  (via drill 0.25, 0.3, 0.3 pad 0.61)  (6 unrouted)
  Top 0.127: 35.87,25.63 U9.26 | 51.64,2.52 51.63,2.53 C9.1
  Top 0.203: 37.52,25.93 37.51,25.92 37.24,25.65 37.26,25.65 | 37.47,25.72 37.47,25.71 35.95,25.71 U9.26 | v53.91,8.2 53.93,8.2 R29.2
  Top 0.254: 16,64.68 15.96,64.64 16.05,64.55 16.05,64.04 | 16.21,63.88 16.08,63.88 | v43.29,36.02 43.29,36.04 43.31,36.02 43.31,35.08 | 43.38,26.76 43.39,26.77 43.24,26.67 | C20.A 16,64.77 15.96,64.77 TP5.1 | 16,64.18 16,61.6 15.69,61.6 | U4.1 U4.2 16.08,60.83 16.08,61.6 15.69,61.6 | 15.69,61.6 C40.2 | 16.95,60.71 U4.2 | U4.3 16.95,60.71 | 16.95,60.71 16.97,60.71 | U3.2 43.15,34.94 43.24,35.03 C35.1 | U3.1 43.65,34.67 43.26,35.05 | U5.2 43.16,25.4 43.39,25.4 | U5.1 43.39,25.4 | C32.1 43.39,26.71 43.39,25.4 | 18.37,59.82 v18.75,59.82 | U4.USM 18.37,59.82 | 18.12,59.82 v17.99,59.82 | 18.37,59.82 18.12,59.82 | 18.12,59.82 18.12,59.69
  Top 0.305: v43.39,27.71 43.39,27.69 | 43.39,27.69 43.39,27.41 | C35.1 43.08,35.03 | C35.1 43.16,35 | 43.24,35.03 43.26,35.03 | 43.39,27.69 43.39,26.77 | v51.57,1.7 51.57,2.54 51.64,2.62 | 51.62,2.57 51.63,2.58 51.63,4.03 U6.5 | 43.24,35.03 43.26,35.05 43.29,35.08 43.31,35.08 | 43.24,35.03 C35.1 | 43.24,35.03 43.21,35 | v38.13,26.57 38.16,26.57 37.26,25.68 37.26,25.65 | v53.91,8.2 53.93,8.18
  Top 0.635: C20.A 16,64.18 15.83,64.01 v14.31,64.01
  Route3 0.203: 53.85,8.26 v53.91,8.2 53.93,8.23 | v51.57,1.7 51.59,1.7
  Route3 0.305: 46.72,18.62 46.77,18.62 46.54,18.62 | 38.18,26.57 v38.13,26.57
  Route3 0.406: v14.31,64.01 15.2,63.12 15.2,59.74 36.63,38.3 36.63,33.73 36.56,33.66 | 46.72,18.62 46.72,20.32 46.16,20.88 43.54,20.88 | 43.54,20.88 43.34,20.88 | v43.39,27.71 43.14,27.97 | v43.39,27.71 43.36,27.71 | v43.39,27.71 43.39,27.74 42.98,28.14 40.87,28.14 40.6,27.86 40.6,26.59 | v45.83,19.18 46.39,18.62 46.77,18.62 48.22,18.62 50.6,16.23 50.6,13.41 | v53.91,8.2 53.88,8.23 53.88,8.26 53.85,8.26 | 53.85,8.26 53.78,8.26 51.16,10.87 51.16,12.85 50.6,13.41 | v51.57,1.7 51.57,1.73 51.54,1.75 53.85,4.06 53.85,8.26 | v49.46,11.99 49.46,12.27 50.6,13.41 | 36.56,33.66 35.72,33.66 34.78,32.72 34.78,28.88 36.3,27.36 37.37,27.36 38.13,26.59 v38.13,26.57 | v43.29,36.02 43.29,35.76 41.18,33.66 36.56,33.66 | 38.18,26.57 38.21,26.59 38.36,26.44 40.6,26.44 40.6,26.59 | 43.54,20.88 43.31,20.88 40.6,23.6 40.6,26.59
  Bottom 0.254: 49.49,10.77 49.41,10.77 49.41,10.73 | U7.5 49.23,10.8 | v45.83,19.18 45.8,19.18 44.98,18.35 R2.1
  Bottom 0.305: v49.46,11.99 49.49,11.99 49.49,10.77 49.49,10.74
  Bottom 0.406: C41.1 49.39,10.7 49.36,10.67 49.23,10.8
  other vias: 18.37,60.58 17.99,61.34 18.75,61.34
  pour Top (isolate 0.254, no thermals): 15.4,60.22 19.13,60.22 19.13,61.72 17.38,61.72 17.38,73.1 13.72,73.1 13.72,62.99 15.4,62.99
  pour Route3 (isolate 0.254): 12.4,74.42 22.82,74.42 22.82,59.44 12.4,59.44
PAR/SER  (via drill 0.25)
  Top 0.127: v28.48,22.56 28.56,22.56
  Top 0.203: U9.8 30.03,24.15 30.03,24.16 29.57,24.16 29.42,24 29.42,22.86 29.17,22.61 28.53,22.61 v28.48,22.56
  Route4 0.381: 43.26,58.67 43.24,58.65 J4.3
  Route4 0.406: v28.48,22.56 30.38,24.46 30.38,28.88 30.97,29.46 33.43,29.46 33.97,30 33.97,41.12 35.01,42.16 35.01,43.18 36.91,45.09 36.91,53.59 41.99,58.67 43.26,58.67
PWR-ON  (via drill 0.25)
  Top 0.127: v58.12,4.19 56.85,5.46 54.31,5.46 54,5.78 54,6.59
  Top 0.203: R29.1 53.94,6.56 53.98,6.6 54,6.59
  Bottom 0.127: J1.97 65.61,5.95 65.61,5.94 65.51,5.84 61.91,5.84 59.95,3.89 58.43,3.89 v58.12,4.19
SCK  (via drill 0.25)
  Top 0.127: 32.67,20.47 v32.67,20.5 32.37,20.8 32.37,22.12 32.24,22.25 32.24,22.5 U9.14 | U9.14 32.25,22.24 | U9.14 32.24,22.49 32.24,22.26
  Route3 0.381: v32.67,20.5 33.18,20.5 35.13,18.54 45.04,18.54 46.31,17.27 46.31,16 v46.26,16
  Route3 0.406: v46.26,16 46.23,16.03
  Route4 0.203: 53.6,58.67 53.55,58.67 J2.4 | 53.6,58.52 53.6,58.67 | 53.6,58.67 53.68,58.67
  Route4 0.406: 53.6,58.51 53.6,58.52 54.74,57.38 54.74,24.51 54.77,24.49 | 54.77,24.49 54.77,24.21 52.41,21.84 52.41,17.78 50.63,16 v46.26,16 | 54.77,24.49
  Bottom 0.254: 45.51,15.94 R1.8 45.52,15.98 45.5,16 v46.26,16
SCL
  Bottom 0.203: U1.6 | U1.6 | U1.6 59.95,7.98 | J1.87 64.27,9.96 64.22,10.01 62.92,10.01 62.34,9.42 | 62.34,8.61 R25.1 62.34,9.42 | 62.34,9.42 62.34,9.45 60.03,9.45 60.03,9.4 59.97,9.34 U1.6
  Bottom 0.254: 60.03,9.45 59.98,9.45 59.52,9.91 58.5,9.91 58.43,9.98 | 58.43,9.98 58.38,10.03 | U7.2 47.76,12.7 | 47.76,12.7 47.73,12.73 | 47.76,12.7 51.47,12.7 52.38,11.79 56.62,11.79 58.43,9.98
SDA  (via drill 0.25)
  Route4 0.406: v61.17,8.81 60.69,9.3 48.67,9.3 46.56,11.41 v46.56,11.43
  Bottom 0.127: 61.3,8.17 61.8,8.17 61.8,8.18 63.07,8.18 63.26,8.37
  Bottom 0.203: 61.3,8.07 61.3,8 | 61.3,8.07 R26.1 | 63.26,8.37 J1.91 | 61.3,8.07 61.3,8.17 | U1.5 60.66,8 60.66,8.07 61.3,8.07
  Bottom 0.254: U1.5 60.66,8 60.66,8.89 61.09,8.89 v61.17,8.81 | 47.89,11.41 47.91,11.43 U7.4 v46.56,11.43
SDI  (via drill 0.25)
  Top 0.127: U9.15 32.75,22.22 32.87,22.1 32.87,21.36 v32.95,21.29 32.88,21.36
  Top 0.254: U9.15
  Route4 0.203: J2.3 51.54,58.52 51.54,58.42 51.64,58.42
  Route4 0.406: v32.95,21.29 33.74,21.29 39.3,15.72 44,15.72 v44.96,16.69 49.49,21.21 49.49,50.7 49.64,50.85 49.64,57 51.16,58.52 51.54,58.52 51.54,58.53
  Bottom 0.254: v44.96,16.69 44.99,16.69 44.99,16 R1.7
SDO  (via drill 0.25)
  Top 0.127: 33.25,22.28 U9.16 | U9.16 33.25,22.53 | U9.16 33.25,22.05 33.48,21.82 33.48,18.42 v33.03,17.96
  Route3 0.406: v43.29,17.78 33.2,17.78 v33.03,17.96
  Bottom 0.254: v43.29,17.78 43.82,17.78 43.87,17.83 R2.2 43.97,17.86 44.02,17.81 | 44.02,17.81 44.05,17.78 | R1.6 44.46,16.15 44.02,16.59 44.02,17.81 | 44.02,17.81 44.02,17.82 R2.2
VAMP  (via drill 0.25, 0.3)
  Top 0.203: C15.1 11.88,27.55 11.89,27.56 12.06,27.39 U10.P4 | U10.P9 16.43,27.39 v16.44,27.41 | 15.86,26.95 15.96,26.95 16.39,27.38 | 16.36,27.38 16,27.02 C12.1 15.98,26.96 15.98,26.95 16.01,26.98 16.01,27.81 15.99,27.8 C11.1
  Top 0.254: U10.P9 15.41,27.39 15.82,26.98 | 16.39,27.38 16.38,27.37 | 15.83,27.81 16.01,27.81 16.03,27.81 v16.44,27.41 | R10.1 17.42,34.15 v16.87,33.6
  Top 0.305: 11.89,27.64 11.89,28.22 v11.87,28.25
  Top 0.406: 16.38,27.37 16.36,27.38 16.39,27.38 16.41,27.41 v16.44,27.41 | v11.87,28.25 11.87,28.04 | 11.89,27.64 11.89,27.56
  Top 0.762: C56.2 1.99,62.23 1.99,63.5 3.26,64.77 TP7.1
  Route3 0.203: 13.82,29.79 13.85,29.79 | 13.82,29.79 13.85,29.82 13.85,30 13.93,30.07 | 13.82,29.79 13.82,29.77 13.85,29.79
  Route3 0.254: v16.44,27.41 16.44,27.43 | 13.27,27.03 13.27,26.85 13.67,26.44 14.48,26.44 15.07,27.03
  Route3 0.406: 16.44,27.43 16.41,27.43 | 13.87,33.73 13.9,33.73 13.85,33.68
  Route3 0.762: 13.87,48.59 13.87,50.34 6.43,57.79 5.8,57.79 3.26,60.33 3.26,64.77 TP7.1
  Route3 0.813: 13.93,33.6 v16.87,33.6 | 13.93,33.6 13.85,33.68 | 13.87,33.73 13.87,48.59 | 13.93,30.07 13.93,33.6
  Bottom 0.203: 15.96,27.1 15.98,27.13 | C7.1 15.96,27.1 | 15.95,26.79 15.95,27.09 15.96,27.1
  Bottom 0.254: 15.95,26.79 16.21,27.05
  Bottom 0.406: 16.41,27.41 16.36,27.41 | C6.1 11.91,28.2 v11.87,28.25 | 16.41,27.41 v16.44,27.41 16.41,27.43 16,27.02 C7.1 | C10.1 16.02,27.8 16.41,27.41
  pour Route3: 10.14,30.35 11.36,31.34 12.38,31.34 13.21,30.51 15.68,30.53 16.14,29.9 16.11,28.09 16.49,27.71 16.49,27 16.16,26.67 16.16,26.21 13.95,23.24 11.51,23.24 10.06,24.49 10.06,26.97 10.09,27.69
VCM  (via drill 0.3)
  Top 0.254: R15.2 30.94,32.06 30.92,32.08 30.56,32.08 30.08,32.56 30.08,32.89 v29.98,33 | R52.2 22.92,27.84 22.89,27.81 22.92,27.79 22.92,27.81 | R53.1 22.92,27.08
  Top 0.406: R52.2 22.92,27.92 22.97,27.86 22.92,27.81 22.92,27.08 22.94,27.43 v22.54,27.46 | R9.2 20.73,35.28 v20.81,35.2
  Route4 0.406: 29.8,33 v29.98,33 29.93,33.05 29.93,33.02 22.56,33.02 | 22.56,33.02 22.56,31.78 21.47,30.68 21.47,28.52 v22.54,27.46 | v20.81,35.2 20.81,34.8 22.59,33.02 22.56,33.02
VDD  (via drill 0.3 pad 0.61, 0.38, 0.61 pad 0.61)  (2 unrouted)
  Top 0.127: 30.26,29.97 30.26,29.59 30.26,29.34 | 30.04,29.47 30.26,29.26 30.26,29.29 30.26,29.34 | 30.26,29.34 30.28,29.31
  Top 0.203: 28.53,21.39 28.53,21.34 28.65,21.45
  Top 0.254: 28.48,21.39 28.53,21.39 28.56,21.39 28.61,21.44 | 30.26,29.29 30.26,29.3 | v27.31,30.68 27.54,30.91 29.32,30.91 30.26,29.97 | 30.28,29.31 30.28,28.77 30.68,28.37 30.74,28.37 30.74,28.31 | 8.97,62.23 9.04,61.4 C16.A 10.24,66.8 TP3.1 | 8.97,62.23 C37.2 | v8.72,62.23 8.97,62.23 | 8.97,62.23 8.98,60.96 U2.2 8.97,60.83 | U2.1 8.97,61.33 8.97,60.83 | U2.3 8.97,60.33 8.97,60.83 | 30.09,23.15 30.05,23.11 | 30.09,23.15 U9.10 | U9.10 U9.9 | U9.10 30.09,23.15 | C26.2 28.65,21.45 30.1,22.91 U9.10 | C25.2 30.15,29.59 30.26,29.59 | v9.99,59.82 9.99,60.58 U2.USM 10.75,60.58 v10.75,59.82
  Top 0.305: v27.77,21.46 27.69,21.39 28.48,21.39
  Route3 0.254: 30.26,23.83 30.26,23.85
  Route3 0.305: v27.77,21.46 27.79,21.46
  Route3 0.406: 39.66,58.85 39.66,58.93 v39.63,58.93 39.71,58.93 39.71,62.99 34.37,68.33 8.72,68.33 v8.72,62.23 | 27.79,21.46 27.74,21.41 28.45,21.41 30.26,23.22 30.26,23.83 | v27.31,30.68 27.67,31.04 29.04,31.04 30.26,29.82 30.26,23.85
  Route3 0.508: v28.28,9.4 26.75,10.92 26.75,20.57 27.64,21.46 v27.77,21.46
  Bottom 0.203: 55.48,58.9 55.4,58.9 55.34,58.97
  Bottom 0.381: 49.87,58.93 49.82,58.88 | 40.98,58.93 R32.2 | v39.63,58.93 39.71,58.93
  Bottom 0.406: v39.63,58.93 39.66,58.95 | 55.48,58.9 55.35,58.93
  Bottom 0.508: 55.4,59 R4.2 55.45,58.93 55.42,58.97 55.34,58.97 | 55.48,58.9 55.48,55.86 54.49,54.86 49.87,54.86 | 47.1,54.86 49.87,54.86 | 47.1,54.86 47.1,58.83 47.07,58.93 R35.2 | 40.98,58.93 39.71,58.93 39.71,56.9 41.74,54.86 47.1,54.86 | 49.87,54.86 49.87,58.93 R33.2 | R19.1 v28.28,9.4
  Bottom 0.61: 16.34,41.15 16.92,40.56 21.29,40.56 23.2,38.74 23.32,38.74 23.45,38.61 23.29,38.65 | 23.29,38.65 23.2,38.35 23.2,34.67 27.24,30.63 27.29,30.68 v27.31,30.68 27.26,30.68 | 23.29,38.65 23.72,38.7 | 8.72,53.85 v8.72,62.23
  Bottom 0.635: 8.72,53.85 16.34,46.23 16.34,41.15
  other vias: 10.37,60.58 9.99,61.34 10.75,61.34
  pour Top (isolate 0.254): 3.26,62.87 4.53,62.87 8.59,66.93 8.59,73.03 11.89,73.03 11.89,66.42 9.23,63.75 9.23,61.72 11.13,61.72 11.13,60.33 3.26,60.33
  pour Route3 (isolate 0.254): 0.59,74.42 11.89,74.42 11.89,59.44 0.59,59.44
VROM
  Bottom 0.203: J1.93 64.73,7.57 63.3,7.57 63.1,7.77 62.57,7.77 62.34,7.54 | 62.34,7.54 R25.2 | 62.34,7.54 62.24,7.7 62.31,7.62 61.88,7.19 61.35,7.19 | 61.35,7.19 61.36,7.17 R26.2 61.18,7.17 61.09,7.09 58.81,7.09 58.65,7.24 58.65,8 | 61.35,7.19 61.32,7.21 | 58.65,8 58.66,8 U1.8 | 58.63,8.03 58.65,8
  Bottom 0.254: 56.98,8.01 56.98,7.87 | C27.1 56.98,8.01 | 58.63,8.03 56.98,8.03 56.98,8.01

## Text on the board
tPlace: VDD | OVDD | GND | +3.3V | LTC2261IUJ-14/LTC6409HUDB | GND | 14-BIT ADC FAMILY | DEMO CIRCUIT 1760A | EXT REF | AIN+ | AIN- | www.linear.com | (408)432-1900 | LTC CONFIDENTIAL- | FOR CUSTOMER USE ONLY | ENCODE | CLK | GND
bPlace: ENCODE | CLK | REV 2
tNames: VAMP | PAR/SER | DIS | ADC SHDN | LVDS | PAR | LVDS | EN | SHDN | SER | CMOS | DIS | RUN | RUN | AMP_SHDN | SHDN
Measures: DRILL TABLE | SYM | SIZE | TOL. | QTY | PLATED | 0.188 in | +/-0.003 in | 4 | YES | 0.070 in | +/-0.003 in | 2 | NO | 2.95" | 0.064 in | +/-0.003 in | 8 | YES | 0.035 in | +/-0.003 in | 12 | YES | 0.032 in | +/-0.003 in | 3 | YES | 0.024 in | +/-0.003 in | 4 | YES | R=0.025" X 2 PLCS | 0.020 in | +/-0.003 in | 11 | YES | 1.915" | 0.016 in | +/-0.003 in | 13 | YES | 0.015 in | +/-0.003 in | 3 | YES | 0.012 in | +/-0.003 in | 22 | YES | D=0.05" | 0.010 in | +/-0.003 in | 1052 | YES | 1.02" | NOTES: UNLESS OTHERWISE SPECIFIED | 0.93" | 1. FAB PER IPC-A-600. | 2. MATERIAL: | LEAD FREE ASSEMBLY COMPLIANT, ISOLA FR-370HR OR EQUIVALENT. | FINISHED THICKNESS TO BE 0.062" +/-0.005" | 6-LAYER BOARD, 2 OZ. CU ON OUTER LAYERS, | 1 OZ. CU ON INNER LAYERS, | FLAMMABILITY RATING: 94 V-2 MINIMUM. | 0.16" | 3. SIZE: | CUT TO DIMENSIONS AND TOLERANCES SHOWN. | 0.00" ARE PRIMARY DATUMS. | 0.00" | INNER LAYERS BROUGHT TO | 4. FINISH: | SMOBC USING WET PHOTO-IMAGEABLE. | EDGE FOR STACKUP INSPECTION | COLOR BLACK FOR THERMAL RADIATION | SILKSCREEN: WHITE NON-CONDUCTIVE EPOXY INK. | 0.00" | 2.40" | 2.45" | 2.66" | GOLD IMMERSION. | 30uIn Au OVER 100uIn LOW STESS Ni ON EDGE FINGERS, | 3-5uIn Au FLASH OR IMMERSION Au MIN. | OVER 100uIn LS Ni ELSEWHERE. | 5. DRILL: | PLATE THRU ALL HOLES WITH COPPER, 0.001" THICK MIN. | ALL HOLES SHALL BE DRILLED +/-0.003" WITH | RESPECT TO CTR. OF DRILLED PAD. | ALL HOLES FINISHED SIZE AFTER PLATING. | 6. DROP ALL UNUSED PADS ON INNER LAYERS. | 7. DO NOT ALTER ARTWORK e.g. TO ADD LOGO OR DATE CODE. | PAD SIZE CAN BE MODIFIED TO MEET END FINISH. | 8. PCBS ARE TO BE RoHS COMPLIANT. | 9. All Cu ALIGNMENT MARKS OUTSIDE THE PCB OUTLINE MUST | BE ROUTED AWAY FOR PROPER CONNECTOR ALIGNMENT | 10. SCORING FOR PANELIZED PCB-PRODUCTION FAB: | 0.017" | 0.02" | XXXXXXXXXXXX | |||||||||||||||||||||||||||||||||||||||||||||||||||||||||||||||||||||||||||||| | XXXXXXXXXXXX | 1 | 1
Document: 2 | PRODUCTION | CLARENCE M. | 01-24-11 | CLARENCE M. | 14-BIT ADC FAMILY | LTC2261IUJ-14/LTC6409HUDB | DEMO CIRCUIT 1760A | 2
Reference: LTC2261IUJ-14/LTC6409HUDB | 14-BIT ADC FAMILY | 1760A | 2
tDocu: MTG1 | MTG2 | NOTES: UNLESS OTHERWISE SPECIFIED | 1. WORKMANSHIP SHALL BE IN ACCORDANCE WITH IPC-A-610. | 2. ASSEMBLY PROCESS SHALL INCLUDE: REFLOW SOLDER TOP SIDE SMD. | MAXIMUM SOLDER TEMPERATURE IS 240 DEGREES CELCIUS. | 3. PARTS TO OMIT WILL BE SPECIFIED ON THE BILL OF MATERIALS. | LOCATIONS OF OMITTED PARTS SHALL BE FREE OF SOLDER. | MASK THE SOLDER STENCIL WHERE SMT PARTS ARE OMITTED. | 4. INSTALL SHUNTS AS SHOWN. | 5. DEPANELIZE BOARDS AFTER ASSEMBLY AND ROUTE-OUT THE | BREAKOUT TABS ON FOUR SIDES OF THE BOARD EDGE. | 6. DO NOT APPLY ANY KIND OF ASSEMBLY STAMP OR QA STAMP | TO ANY BOARD. | 7. INSTALL 4 STANDOFFS ON MTG1-MTG4 AND FROM THE BOTTOM SIDE. | MTG3 | MTG4 | 1 | 2
bDocu: CLARENCE M. | 14-BIT ADC FAMILY | LTC2261IUJ-14/LTC6409HUDB | 2 | DEMO CIRCUIT 1760A | 2 | 2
